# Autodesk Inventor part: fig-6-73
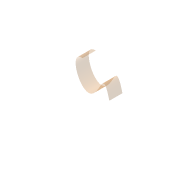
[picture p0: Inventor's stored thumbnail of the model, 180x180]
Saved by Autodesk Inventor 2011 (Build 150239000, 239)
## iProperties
Shininess: 64.0
Length Units: 11269
Angle Units: 11279
Time Units: 11290
Mass Units: 11283
Length Display Precision: 3
Angle Display Precision: 2
Compacted: True
Part Number: fig-6-73
Document SubType Name: Modeling
Created: 2002-12
Designer: deepak
Density: 1 g/cm^3
Density: 0.0
Volumn: 0.0
Area: 0.0
PropertySet Name: Model Information
Control State: 0
Master: False
Checked Out: False
Author: deepak
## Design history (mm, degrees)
sketch "Sketch1"
  geometry: 5 further points
  constraints: 5 other
extrude_surface "ExtrusionSrf1" sketch "Sketch1" dims "d0" = 20, "d1" = 0
body "Srf1"
